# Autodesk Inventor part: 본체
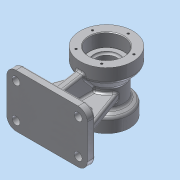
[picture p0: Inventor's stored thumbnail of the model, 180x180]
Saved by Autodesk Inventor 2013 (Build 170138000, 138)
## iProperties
Created: 2015-08
Part Number: 본체
Material: 알루미늄 6061
Document SubType Name: Modeling
Designer: Administrator
Mass: 1059.11 g
Surface Area: 750.406 cm^2
Volume: 390.815 cm^3
Density: 2.71 g/cm^3
Author: Administrator
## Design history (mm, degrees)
sketch "스케치1"
  geometry: L1 (14, 0)-(108, 0); L2 (122, 14)-(122, 66); L3 (108, 80)-(14, 80); L4 (0, 66)-(0, 14); C1 r 6 at (14, 66); C2 r 6 at (108, 66); C3 r 6 at (108, 14); C4 r 6 at (14, 14); A1 r 14 centre (14, 66) between (14, 80) and (0, 66); A2 r 14 centre (108, 66) between (122, 66) and (108, 80); A3 r 14 centre (108, 14) between (108, 0) and (122, 14); A4 r 14 centre (14, 14) between (0, 14) and (14, 0); 4 further points
  constraints: 8 centre point, 8 end point, 8 point on circle, 8 point on line, 8 tangent, 4 coincident, 3 equal radius, 2 parallel, 1 horizontal, 1 perpendicular
  dimensions: "d0" = 122 distance of point (0, 80) point (122, 80); "d1" = 80 distance of point (122, 80) point (122, 0); "d2" = 14 radius of A1; "d3" = 12 diameter of C1; "d4" = 12 diameter of C2; "d5" = 12 diameter of C3; "d6" = 12 diameter of C4
extrude "돌출1" new body sketch "스케치1" distance "d7" = 12; taper "d8" = 0 deg
node "작업 평면1"
sketch "스케치2"
  geometry: L1 (108, 12)-(108, 0) reference; L2 (108, 0)-(-14, 0) reference; L3 (-14, 0)-(-14, 12) reference; L4 (-14, 12)-(108, 12) reference; L5 (-14, 12)-(-4, 12); L6 (-4, 12)-(26.782, 96.572); L7 (47, 0)-(47, 33.484); L8 (47, 12)-(23, 12); L9 (23, 12)-(23, 30); L10 (23, 30)-(23, 24); L11 (23, 24)-(23, 24); L12 (29, 30)-(29, 36); L13 (23, 42)-(23, 42); L14 (17, 36)-(17, 30); L15 (23, 24)-(23, 24); L16 (77, 36)-(77, 30); L17 (65, 30)-(65, 36); L18 (71, 42)-(71, 42); L19 (98, 12)-(67.218, 96.572); L20 (71, 30)-(71, 24); L21 (71, 24)-(71, 24); L22 (71, 24)-(71, 24); L23 (71, 12)-(71, 30); L24 (26.782, 96.572)-(67.218, 96.572); L25 (-4, 12)-(98, 12); A1 r 6 centre (23, 36) between (29, 36) and (23, 42); A2 r 6 centre (23, 36) between (23, 42) and (17, 36); A3 r 6 centre (23, 30) between (17, 30) and (23, 24); A4 r 6 centre (23, 30) between (23, 24) and (29, 30); A5 r 6 centre (71, 30) between (71, 24) and (77, 30); A6 r 6 centre (71, 36) between (71, 42) and (65, 36); A7 r 6 centre (71, 36) between (77, 36) and (71, 42); A8 r 6 centre (71, 30) between (65, 30) and (71, 24); 8 further points
  constraints: 42 end point, 21 point on line, 21 symmetric about line, 16 point on circle, 8 centre point, 8 tangent, 5 perpendicular, 3 equal radius, 3 parallel, 2 midpoint, 4 other
  dimensions: "d9" = 10 distance of L3.end L5.end; "d10" = 90 distance of L5.end L6.end; "d11" = 110 deg angle of L6 L5; "d12" = 24 distance of L8.start L8.end; "d13" = 18 distance of L8.end L9.end; "d14" = 6 distance of L9.end L10.end; "d15" = 6 distance of L10.end point (29, 24); "d16" = 18 distance of point (29, 24) point (29, 42); "d17" = 12 distance of point (29, 42) point (17, 42); "d18" = 18 distance of point (17, 42) point (17, 24); "d19" = 6 radius of A1
extrude "돌출2" join sketch "스케치2" stored distance "d20" = 12; taper "d21" = 0 deg
node "작업 평면2"
extrude "돌출3" join sketch "스케치3" stored distance "d26" = 12; taper "d27" = 0 deg
sketch "스케치5"
  geometry: L1 (94, 0)-(0, 0) reference; L2 (0, 0)-(0, 12) reference; L3 (47, 0)-(47, 90); C1 r 35 at (47, 90); 1 further point
  constraints: 2 end point, 1 centre point, 1 coincident, 1 midpoint, 1 parallel
  dimensions: "d38" = 90 distance of L3.start L3.end; "d39" = 70 diameter of C1
extrude "돌출4" join sketch "스케치5" distance "d40" = 20; taper "d41" = 0 deg
sketch "스케치6"
  geometry: L1 (-108, 12)-(-94, 12) reference; L2 (-94, 12)-(-53, 12) reference; L3 (-53, 12)-(-53, 55.518) reference; L4 (-41, 80.937)-(-41, 55.518) reference; L5 (-53, 80.937)-(-41, 80.937) reference; L6 (-53, 55.518)-(-53, 80.937) reference; L7 (-108, 0)-(-108, 12) reference; L8 (-94, 0)-(-108, 0) reference; L9 (-94, 12)-(-94, 0) reference; L10 (-41, 55.518)-(-41, 12) reference; L11 (-41, 12)-(0, 12) reference; L12 (0, 12)-(0, 0) reference; L13 (0, 0)-(-94, 0) reference; L14 (0, 12)-(14, 12) reference; L15 (14, 12)-(14, 0) reference; L16 (14, 0)-(0, 0) reference; C1 r 26 at (-47, 90); A1 r 35 centre (-47, 90) between (-41, 55.518) and (-53, 55.518) reference
  constraints: 1 centre point, 1 coincident
  dimensions: "d42" = 52 diameter of C1
extrude "돌출5" join sketch "스케치6" distance "d43" = 70; taper "d44" = 0 deg
sketch "스케치7"
  geometry: C1 r 26 at (0, 0) reference; C2 r 40 at (0, 0); 1 further point
  constraints: 1 centre point, 1 coincident
  dimensions: "d45" = 80 diameter of C2
extrude "돌출6" join sketch "스케치7" distance "d46" = 20; taper "d47" = 0 deg
sketch "스케치8"
  geometry: L1 (-4, 55)-(-14, 55) reference; L2 (-14, 55)-(-14, 125) reference; L3 (-14, 125)-(6, 125) reference; L4 (6, 125)-(6, 116) reference; L5 (6, 116)-(56, 116) reference; L6 (56, 116)-(56, 130) reference; L7 (56, 130)-(76, 130) reference; L8 (76, 130)-(76, 50) reference; L9 (76, 50)-(62.7, 50) reference; L10 (62.7, 50)-(56, 12) reference; L11 (56, 12)-(66, 12) reference; L12 (66, 12)-(66, 0) reference; L13 (66, 0)-(-14, 0) reference; L14 (-14, 0)-(-14, 12) reference; L15 (-14, 12)-(-4, 12) reference; L16 (-4, 12)-(-4, 55) reference; L17 (6, 125)-(11.196, 116); L18 (6, 116)-(6, 125); L19 (6, 116)-(11.196, 116); L20 (56, 130)-(39.315, 116); L21 (39.315, 116)-(56, 116); L22 (56, 116)-(56, 130); L23 (-14, 90)-(21.602, 90)
  constraints: 14 end point, 2 collinear, 2 point on line, 1 midpoint, 1 perpendicular
  dimensions: "d49" = 60 deg angle of L19 L17; "d50" = 40 deg angle of L5 L20
revolve "회전2" sketch "스케치8" stored, may be unused: angle "d51" = 90 deg
sketch "스케치9"
  geometry: C1 r 40 at (0, 0) reference; C2 r 16 at (0, 0); 1 further point
  constraints: 1 centre point, 1 coincident
  dimensions: "d52" = 32 diameter of C2
extrude "돌출7" cut sketch "스케치9" distance "d54" = 90; taper "d55" = 0 deg
sketch "스케치10"
  geometry: C1 r 16 at (0, 0) reference; C2 r 40 at (0, 0) reference; C3 r 19 at (0, 0); 1 further point
  constraints: 1 centre point, 1 coincident
  dimensions: "d56" = 38 diameter of C3
extrude "돌출8" cut sketch "스케치10" distance "d57" = 23; taper "d58" = 0 deg
sketch "스케치11"
  geometry: C1 r 19 at (0, 0) reference; C2 r 40 at (0, 0) reference; C3 r 26 at (0, 0); 1 further point
  constraints: 1 centre point, 1 coincident
  dimensions: "d59" = 52 diameter of C3
extrude "돌출9" cut sketch "스케치11" distance "d60" = 20; taper "d61" = 0 deg
sketch "스케치12"
  geometry: C1 r 16 at (0, 0) reference; C2 r 35 at (0, 0) reference; C3 r 20 at (0, 0); 1 further point
  constraints: 1 centre point, 1 coincident
  dimensions: "d62" = 40 diameter of C3
extrude "돌출10" cut sketch "스케치12" distance "d63" = 17; taper "d64" = 0 deg
sketch "스케치13"
  geometry: L1 (0, 0)-(0, 33); C1 r 40 at (0, 0) reference; 1 further point
  constraints: 2 end point, 1 vertical
  dimensions: "d65" = 33 distance of L1.start L1.end
hole "구멍1" sketch "스케치13" at (0, 33) diameter "d66" = 3.242; stored, may be unused: countersink angle "d70" = 90 deg, drill point angle "d72" = 118 deg; dims "d67" = 10, "d68" = 4, "d69" = 2, "d71" = 13
sketch "스케치14"
  geometry: L1 (0, 0)-(0, 27); C1 r 35 at (0, 0) reference; 1 further point
  constraints: 2 end point, 1 vertical
  dimensions: "d76" = 27 distance of L1.start L1.end
hole "구멍2" sketch "스케치14" at (0, 27) diameter "d77" = 3.242; stored, may be unused: countersink angle "d81" = 90 deg, drill point angle "d83" = 118 deg; dims "d78" = 10, "d79" = 4, "d80" = 2, "d82" = 13
fillet "모깎기1" dims "d90" = 5
fillet "모깎기2" dims "d91" = 3
chamfer "모따기1" distance "d92" = 1; stored, may be unused: second distance "d93" = 2, angle "d94" = 45 deg
fillet "모깎기3" dims "d95" = 0.3
sketch "스케치15"
  geometry: L1 (3.113, 55.518)-(-4, 55.518) reference; L2 (-4, 55.518)-(-14, 55.518) reference; L3 (-14, 55.518)-(-14, 69.875) reference; L4 (-13, 70.921)-(2.7, 70.921) reference; L5 (3, 71.236)-(3, 75.168) reference; L6 (3, 75.168)-(53, 75.168) reference; L7 (56, 71.972)-(56, 65.01) reference; L8 (56.3, 64.702)-(75, 64.702) reference; L9 (76, 63.675)-(76, 50.453) reference; L10 (76, 50.453)-(62.78, 50.453) reference; L11 (62.78, 50.453)-(56, 12) reference; L12 (56, 12)-(66, 12) reference; L13 (66, 12)-(66, 0) reference; L14 (66, 0)-(-14, 0) reference; L15 (-14, 0)-(-14, 12) reference; L16 (-14, 12)-(-4, 12) reference; L17 (-4, 12)-(20, 12) reference; L18 (20, 12)-(20, 64.702) reference; L19 (20, 64.702)-(14.083, 64.702) reference; L20 (-4, 12)-(-4, 55.518) reference; L21 (62.78, 50.453)-(57.82, 50.453) reference; L22 (37.496, 64.702)-(32, 64.702) reference; L23 (32, 64.702)-(32, 12) reference; L24 (32, 12)-(56, 12) reference; L25 (14.083, 115.298)-(37.496, 115.298) reference; L26 (57.82, 129.547)-(76, 129.547) reference; L27 (76, 129.547)-(76, 116.325) reference; L28 (75, 115.298)-(56.3, 115.298) reference; L29 (56, 114.99)-(56, 108.028) reference; L30 (53, 104.832)-(3, 104.832) reference; L31 (3, 104.832)-(3, 108.764) reference; L32 (2.7, 109.079)-(-13, 109.079) reference; L33 (-14, 110.125)-(-14, 124.482) reference; L34 (-14, 124.482)-(3.113, 124.482) reference; L35 (-4, 12)-(12, 12); L36 (12, 12)-(12, 36); 9 further points
  constraints: 4 end point, 1 coincident, 1 perpendicular, 1 point on line, 23 other
  dimensions: "d96" = 16 distance of L16.end L35.end; "d97" = 24 distance of L35.end L36.end
feature "엠보싱1" sketch "스케치15" dims "d0" = 122, "d1" = 80, "d2" = 14, "d3" = 12, "d4" = 12, "d5" = 12, "d6" = 12, "d98" = 0.5, "d99" = 0
fillet "모깎기4" dims "d100" = 3
fillet "모깎기5" dims "d101" = 3
fillet "모깎기6" dims "d102" = 3
node "솔리드1"
pattern_circular "원형 패턴2" dims angle "d85" = 360 deg
pattern_circular "원형 패턴3" dims angle "d88" = 360 deg
node "절단 모서리 투영1"
node "절단 모서리 투영12"
node "절단 모서리 투영13"
node "절단 모서리 투영14"
other parameters: "d24" = 80 deg
